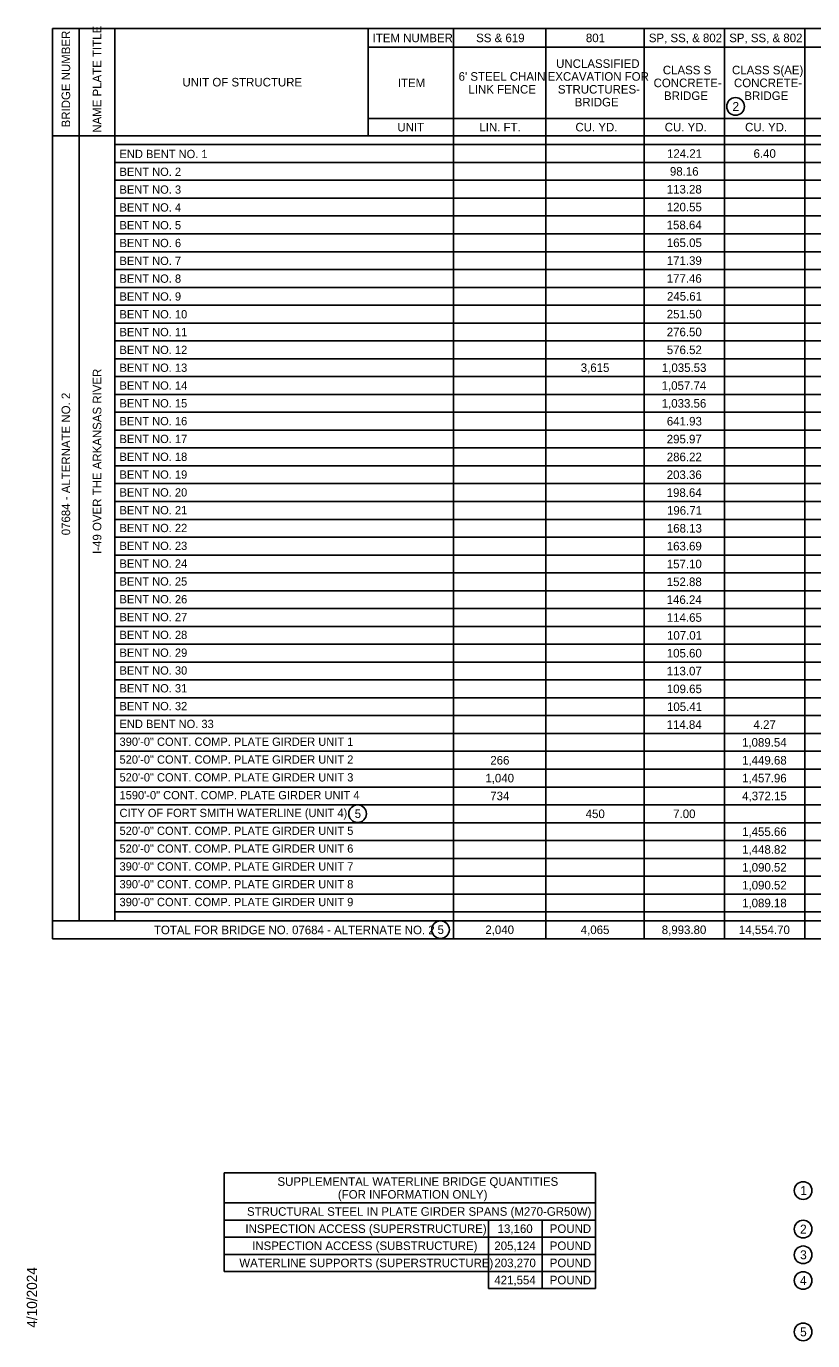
# Model space of a CAD drawing. Extents: x 0.06 to 1.36, y 0.04 to 0.85.
# Drawn here: x 0.06 to 0.519, y 0.071 to 0.838 of the extents above; entities that cross this region are included whole.
import ezdxf

# ---------------------------------------------------------------- set-up
doc = ezdxf.new("R2010")
doc.units = 0
for name, color, linetype in [('R_Shade By Others', 7, 'Continuous'), ('R_Survey Control', 7, 'Continuous'), ('R_Wall', 7, 'Continuous')]:
    doc.layers.add(name, color=color, linetype=linetype)

msp = doc.modelspace()

# ---------------------------------------------------------------- linework, layer by layer
at = {"layer": 'R_Survey Control'}
for p, q in [((0.07508, 0.3057), (0.07508, 0.83695)), ((0.07508, 0.83695), (1.33392, 0.83695)), ((0.09071, 0.31612), (0.09071, 0.83695)), ((0.11154, 0.31612), (0.11154, 0.83695)), ((0.11154, 0.77445), (0.11154, 0.83695)), ((0.2593, 0.77445), (0.2593, 0.83695)), ((0.30915, 0.83695), (0.30915, 0.3057)), ((0.36311, 0.83695), (0.36311, 0.3057)), ((0.4204, 0.83695), (0.4204, 0.3057)), ((0.46733, 0.83695), (0.46733, 0.3057)), ((0.51421, 0.83695), (0.51421, 0.3057)), ((0.2593, 0.78445), (1.33392, 0.78445)), ((0.07508, 0.77445), (1.33392, 0.77445)), ((0.11154, 0.76924), (1.33392, 0.76924)), ((0.11154, 0.75883), (1.33392, 0.75883)), ((0.11154, 0.74841), (1.33392, 0.74841)), ((0.11154, 0.73799), (1.33392, 0.73799)), ((0.11154, 0.72758), (1.33392, 0.72758)), ((0.11154, 0.71716), (1.33392, 0.71716)), ((0.11154, 0.70674), (1.33392, 0.70674)), ((0.11154, 0.69633), (1.33392, 0.69633)), ((0.11154, 0.68591), (1.33392, 0.68591)), ((0.11154, 0.67549), (1.33392, 0.67549)), ((0.11154, 0.66508), (1.33392, 0.66508)), ((0.11154, 0.65466), (1.33392, 0.65466)), ((0.11154, 0.64424), (1.33392, 0.64424)), ((0.11154, 0.63383), (1.33392, 0.63383)), ((0.11154, 0.62341), (1.33392, 0.62341)), ((0.11154, 0.61299), (1.33392, 0.61299)), ((0.11154, 0.60258), (1.33392, 0.60258)), ((0.11154, 0.59216), (1.33392, 0.59216)), ((0.11154, 0.58174), (1.33392, 0.58174)), ((0.11154, 0.57133), (1.33392, 0.57133)), ((0.11154, 0.56091), (1.33392, 0.56091)), ((0.11154, 0.55049), (1.33392, 0.55049)), ((0.11154, 0.54008), (1.33392, 0.54008)), ((0.11154, 0.52966), (1.33392, 0.52966)), ((0.11154, 0.51924), (1.33392, 0.51924)), ((0.11154, 0.50883), (1.33392, 0.50883)), ((0.11154, 0.49841), (1.33392, 0.49841)), ((0.11154, 0.48799), (1.33392, 0.48799)), ((0.11154, 0.47758), (1.33392, 0.47758)), ((0.11154, 0.46716), (1.33392, 0.46716)), ((0.11154, 0.45674), (1.33392, 0.45674)), ((0.11154, 0.44633), (1.33392, 0.44633)), ((0.11154, 0.43591), (1.33392, 0.43591)), ((0.11154, 0.42549), (1.33392, 0.42549)), ((0.11154, 0.41508), (1.33392, 0.41508)), ((0.11154, 0.40466), (1.33392, 0.40466)), ((0.11154, 0.39424), (1.33392, 0.39424)), ((0.11154, 0.38383), (1.33392, 0.38383)), ((0.11154, 0.37341), (1.33392, 0.37341)), ((0.11154, 0.36299), (1.33392, 0.36299)), ((0.11154, 0.35258), (1.33392, 0.35258)), ((0.11154, 0.34216), (1.33392, 0.34216)), ((0.11154, 0.33174), (1.33392, 0.33174)), ((0.07508, 0.31612), (1.33392, 0.31612)), ((0.11154, 0.32133), (1.33392, 0.32133)), ((0.07508, 0.3057), (1.33392, 0.3057)), ((0.17537, 0.16895), (0.17537, 0.11145)), ((0.17537, 0.16895), (0.39204, 0.16895)), ((0.39204, 0.16895), (0.39204, 0.10145)), ((0.17537, 0.15145), (0.39204, 0.15145)), ((0.17537, 0.14145), (0.39204, 0.14145)), ((0.32954, 0.14145), (0.32954, 0.10145)), ((0.36079, 0.14145), (0.36079, 0.10145)), ((0.17537, 0.13145), (0.39204, 0.13145)), ((0.17537, 0.12145), (0.39204, 0.12145)), ((0.17537, 0.11145), (0.39204, 0.11145)), ((0.32954, 0.10145), (0.39204, 0.10145))]:
    msp.add_line(p, q, dxfattribs=at)
msp.add_lwpolyline([(0.2593, 0.82612), (0.30758, 0.82612), (0.41883, 0.82612), (0.46733, 0.82612), (0.509, 0.82612), (0.55587, 0.82612), (0.58452, 0.82612), (0.6366, 0.82612), (0.68087, 0.82612), (0.74858, 0.82612), (0.79433, 0.82612), (0.84642, 0.82612), (0.94537, 0.82612), (1.00267, 0.82612), (1.06517, 0.82612), (1.19277, 0.82612), (1.26048, 0.82612), (1.31256, 0.82612), (1.33392, 0.82612)], dxfattribs=at)
at = {"layer": 'R_Wall'}
for p, q in [((0.07508, 0.77445), (0.09071, 0.77445)), ((0.09071, 0.77445), (0.11154, 0.77445))]:
    msp.add_line(p, q, dxfattribs=at)
for centre in [(0.47374, 0.79152), (0.25316, 0.37868), (0.30155, 0.31097), (0.51317, 0.15868), (0.51317, 0.13618), (0.51317, 0.12118), (0.51317, 0.10618), (0.51317, 0.07618)]:
    msp.add_circle(centre, 0.00515, dxfattribs=at)

# ---------------------------------------------------------------- texts
at = {"layer": 'R_Shade By Others'}
msp.add_text('4/10/2024', height=0.00595, rotation=89.99995, dxfattribs=at).set_placement((0.06607, 0.0786))
at = {"layer": 'R_Survey Control'}
for s, p in [('NAME PLATE TITLE', (0.10362, 0.77619)), ('BRIDGE NUMBER', (0.0854, 0.77929)), ('I-49 OVER THE ARKANSAS RIVER', (0.10362, 0.53031)), ('07684 - ALTERNATE NO. 2', (0.0854, 0.54119))]:
    msp.add_text(s, height=0.005, rotation=90, dxfattribs=at).set_placement(p)
for s, height, p in [('ITEM NUMBER', 0.005, (0.26194, 0.82904)), ('SS & 619', 0.005, (0.32235, 0.82904)), ('801', 0.005, (0.3864, 0.82904)), ('SP, SS, & 802', 0.005, (0.42313, 0.82904)), ('SP, SS, & 802', 0.005, (0.47003, 0.82904)), ('UNCLASSIFIED', 0.005, (0.36903, 0.81404)), ('CLASS S ', 0.005, (0.4313, 0.81029)), ('CLASS S(AE)', 0.005, (0.47167, 0.81029)), ('UNIT OF STRUCTURE', 0.005, (0.15095, 0.8032)), ('ITEM', 0.005, (0.27661, 0.80279)), ("6' STEEL CHAIN", 0.005, (0.31212, 0.80654)), ('EXCAVATION FOR ', 0.005, (0.36408, 0.80654)), ('CONCRETE-', 0.005, (0.42591, 0.80279)), ('CONCRETE-', 0.005, (0.47282, 0.80279)), ('LINK FENCE', 0.005, (0.31785, 0.79904)), ('STRUCTURES-', 0.005, (0.37004, 0.79904)), ('BRIDGE', 0.005, (0.43198, 0.79529)), ('BRIDGE', 0.005, (0.47888, 0.79529)), ('BRIDGE', 0.005, (0.37987, 0.79154)), ('UNIT', 0.005, (0.27638, 0.77695)), ('LIN. FT.', 0.005, (0.32421, 0.77695)), ('CU. YD.', 0.005, (0.38029, 0.77695)), ('CU. YD.', 0.005, (0.4324, 0.77695)), ('CU. YD.', 0.005, (0.4793, 0.77695)), ('END BENT NO. 1', 0.0048358, (0.11421, 0.76137)), ('124.21', 0.005, (0.43372, 0.76154)), ('6.40', 0.005, (0.48424, 0.76154)), ('BENT NO. 2', 0.004836, (0.11421, 0.75098)), ('98.16', 0.005, (0.43543, 0.75112)), ('BENT NO. 3', 0.004836, (0.11421, 0.74058)), ('113.28', 0.005, (0.43357, 0.7407)), ('BENT NO. 4', 0.004836, (0.11421, 0.73018)), ('120.55', 0.005, (0.43362, 0.73029)), ('BENT NO. 5', 0.004836, (0.11421, 0.71979)), ('158.64', 0.005, (0.43353, 0.71987)), ('BENT NO. 6', 0.004836, (0.11421, 0.70939)), ('165.05', 0.005, (0.43362, 0.70945)), ('BENT NO. 7', 0.004836, (0.11421, 0.69899)), ('171.39', 0.005, (0.43359, 0.69904)), ('BENT NO. 8', 0.004836, (0.11421, 0.6886)), ('177.46', 0.005, (0.43356, 0.68862)), ('BENT NO. 9', 0.004836, (0.11421, 0.6782)), ('245.61', 0.005, (0.43372, 0.6782)), ('BENT NO. 10', 0.0048358, (0.11421, 0.6678)), ('251.50', 0.005, (0.43358, 0.66779)), ('BENT NO. 11', 0.0048358, (0.11421, 0.65741)), ('276.50', 0.005, (0.43358, 0.65737)), ('BENT NO. 12', 0.0048358, (0.11421, 0.64701)), ('576.52', 0.005, (0.4336, 0.64695)), ('BENT NO. 13', 0.0048358, (0.11421, 0.63661)), ('3,615', 0.005, (0.38339, 0.63654)), ('1,035.53', 0.005, (0.43072, 0.63654)), ('BENT NO. 14', 0.0048358, (0.11421, 0.62621)), ('1,057.74', 0.005, (0.43061, 0.62612)), ('BENT NO. 15', 0.0048358, (0.11421, 0.61582)), ('1,033.56', 0.005, (0.43064, 0.6157)), ('BENT NO. 16', 0.0048358, (0.11421, 0.60542)), ('641.93', 0.005, (0.43364, 0.60529)), ('BENT NO. 17', 0.0048358, (0.11421, 0.59502)), ('295.97', 0.005, (0.43357, 0.59487)), ('BENT NO. 18', 0.0048358, (0.11421, 0.58463)), ('286.22', 0.005, (0.4336, 0.58445)), ('BENT NO. 19', 0.0048358, (0.11421, 0.57423)), ('203.36', 0.005, (0.43356, 0.57404)), ('BENT NO. 20', 0.0048358, (0.11421, 0.56383)), ('198.64', 0.005, (0.43353, 0.56362)), ('BENT NO. 21', 0.0048358, (0.11421, 0.55344)), ('196.71', 0.005, (0.43372, 0.5532)), ('BENT NO. 22', 0.0048358, (0.11421, 0.54304)), ('168.13', 0.005, (0.43364, 0.54279)), ('BENT NO. 23', 0.0048358, (0.11421, 0.53264)), ('163.69', 0.005, (0.43359, 0.53237)), ('BENT NO. 24', 0.0048358, (0.11421, 0.52225)), ('157.10', 0.005, (0.43358, 0.52195)), ('BENT NO. 25', 0.0048358, (0.11421, 0.51185)), ('152.88', 0.005, (0.43357, 0.51154)), ('BENT NO. 26', 0.0048358, (0.11421, 0.50145)), ('146.24', 0.005, (0.43353, 0.50112)), ('BENT NO. 27', 0.0048358, (0.11421, 0.49105)), ('114.65', 0.005, (0.43362, 0.4907)), ('BENT NO. 28', 0.0048358, (0.11421, 0.48066)), ('107.01', 0.005, (0.43372, 0.48029)), ('BENT NO. 29', 0.0048358, (0.11421, 0.47026)), ('105.60', 0.005, (0.43358, 0.46987)), ('BENT NO. 30', 0.0048358, (0.11421, 0.45986)), ('113.07', 0.005, (0.43357, 0.45945)), ('BENT NO. 31', 0.0048358, (0.11421, 0.44947)), ('109.65', 0.005, (0.43362, 0.44904)), ('BENT NO. 32', 0.0048358, (0.11421, 0.43907)), ('105.41', 0.005, (0.43372, 0.43862)), ('END BENT NO. 33', 0.0048358, (0.11421, 0.42867)), ('114.84', 0.005, (0.43353, 0.4282)), ('4.27', 0.005, (0.48422, 0.4282)), ('390\'-0" CONT. COMP. PLATE GIRDER UNIT 1', 0.0048358, (0.11421, 0.41828)), ('1,089.54', 0.005, (0.47752, 0.41779)), ('520\'-0" CONT. COMP. PLATE GIRDER UNIT 2', 0.0048358, (0.11421, 0.40788)), ('266', 0.005, (0.33061, 0.40737)), ('1,449.68', 0.005, (0.47756, 0.40737)), ('520\'-0" CONT. COMP. PLATE GIRDER UNIT 3', 0.0048358, (0.11421, 0.39748)), ('1,040', 0.005, (0.32772, 0.39695)), ('1,457.96', 0.005, (0.47755, 0.39695)), ('1590\'-0" CONT. COMP. PLATE GIRDER UNIT 4', 0.0048358, (0.11421, 0.38708)), ('734', 0.005, (0.33058, 0.38654)), ('4,372.15', 0.005, (0.47761, 0.38654)), ('CITY OF FORT SMITH WATERLINE (UNIT 4)', 0.0048358, (0.11421, 0.37669)), ('450', 0.005, (0.38626, 0.37612)), ('7.00', 0.005, (0.43733, 0.37612)), ('520\'-0" CONT. COMP. PLATE GIRDER UNIT 5', 0.0048358, (0.11421, 0.36629)), ('1,455.66', 0.005, (0.47755, 0.3657)), ('520\'-0" CONT. COMP. PLATE GIRDER UNIT 6', 0.0048358, (0.11421, 0.35589)), ('1,448.82', 0.005, (0.47758, 0.35529)), ('390\'-0" CONT. COMP. PLATE GIRDER UNIT 7', 0.0048358, (0.11421, 0.3455)), ('1,090.52', 0.005, (0.47758, 0.34487)), ('390\'-0" CONT. COMP. PLATE GIRDER UNIT 8', 0.0048358, (0.11421, 0.3351)), ('1,090.52', 0.005, (0.47758, 0.33445)), ('390\'-0" CONT. COMP. PLATE GIRDER UNIT 9', 0.0048358, (0.11421, 0.3247)), ('1,089.18', 0.005, (0.47756, 0.32404)), ('TOTAL FOR BRIDGE NO. 07684 - ALTERNATE NO. 2', 0.005, (0.13429, 0.30834)), ('2,040', 0.005, (0.32772, 0.30841)), ('4,065', 0.005, (0.38339, 0.30841)), ('8,993.80', 0.005, (0.43066, 0.30841)), ('14,554.70', 0.005, (0.47569, 0.30841)), ('SUPPLEMENTAL WATERLINE BRIDGE QUANTITIES', 0.005, (0.2064, 0.16145)), ('(FOR INFORMATION ONLY)', 0.005, (0.24166, 0.15395)), ('STRUCTURAL STEEL IN PLATE GIRDER SPANS (M270-GR50W)', 0.005, (0.1886, 0.14395)), ('INSPECTION ACCESS (SUPERSTRUCTURE)', 0.005, (0.18768, 0.13395)), ('13,160', 0.005, (0.33488, 0.13395)), ('POUND', 0.005, (0.36531, 0.13395)), ('INSPECTION ACCESS (SUBSTRUCTURE)', 0.005, (0.19161, 0.12395)), ('205,124', 0.005, (0.33295, 0.12395)), ('POUND', 0.005, (0.36531, 0.12395)), ('WATERLINE SUPPORTS (SUPERSTRUCTURE)', 0.005, (0.18413, 0.11395)), ('203,270', 0.005, (0.333, 0.11395)), ('POUND', 0.005, (0.36531, 0.11395)), ('421,554', 0.005, (0.33295, 0.10395)), ('POUND', 0.005, (0.36531, 0.10395))]:
    msp.add_text(s, height=height, dxfattribs=at).set_placement(p)
at = {"layer": 'R_Wall'}
for s, height, p in [('2', 0.00521, (0.47194, 0.78892)), ('5', 0.005, (0.25146, 0.37618)), ('5', 0.005, (0.29985, 0.30847)), ('1', 0.00521, (0.51151, 0.15608)), ('2', 0.00521, (0.51138, 0.13358)), ('3', 0.00521, (0.51142, 0.11858)), ('4', 0.00521, (0.51131, 0.10358)), ('5', 0.00521, (0.51141, 0.07358))]:
    msp.add_text(s, height=height, dxfattribs=at).set_placement(p)

doc.saveas('drawing.dxf')
